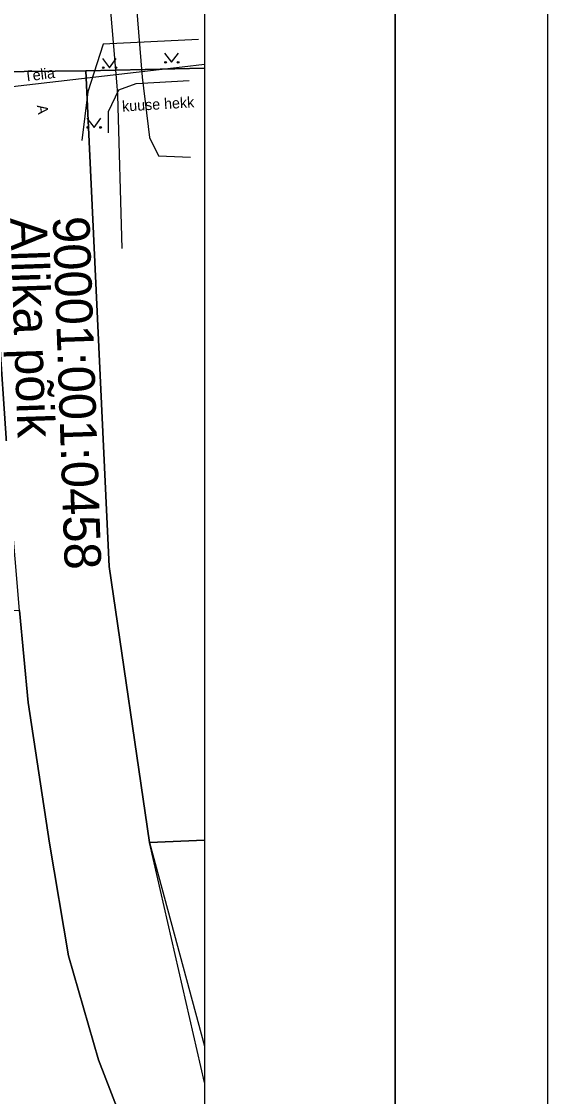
# Model space of a CAD drawing. Extents: x 648017 to 648227, y 6561313 to 6561610.
# Drawn here: x 648192.3 to 648226.8, y 6561440.1 to 6561510.6 of the extents above; entities that cross this region are included whole.
import ezdxf

# ---------------------------------------------------------------- set-up
doc = ezdxf.new("R2010")
doc.units = 0
for name, color, linetype in [('HALJASTUS', 7, 'Continuous'), ('PIIR', 7, 'Continuous'), ('SITRASS', 7, 'Continuous'), ('TEE', 7, 'Continuous'), ('VORMISTUS', 7, 'Continuous')]:
    doc.layers.add(name, color=color, linetype=linetype)

msp = doc.modelspace()

# ---------------------------------------------------------------- linework, layer by layer
at = {"layer": 'HALJASTUS'}
for p, q in [((648201.663, 6561508.575), (648202.126, 6561507.968)), ((648202.126, 6561507.968), (648202.572, 6561508.575)), ((648197.585, 6561508.218), (648198.048, 6561507.611)), ((648198.048, 6561507.611), (648198.494, 6561508.218)), ((648196.575, 6561504.296), (648197.038, 6561503.689)), ((648197.038, 6561503.689), (648197.484, 6561504.296))]:
    msp.add_line(p, q, dxfattribs=at)
msp.add_lwpolyline([(648197.976, 6561503.349), (648197.983, 6561504.737), (648198.654, 6561506.15), (648199.801, 6561506.568), (648203.285, 6561506.778)], dxfattribs=at)
for centre in [(648201.725, 6561507.968), (648202.554, 6561507.968), (648197.647, 6561507.611), (648198.476, 6561507.611), (648196.637, 6561503.689), (648197.466, 6561503.689)]:
    msp.add_circle(centre, 0.055, dxfattribs=at)
at = {"layer": 'PIIR'}
for points in [[(648204.275, 6561507.585), (648196.49, 6561507.4), (648190.43, 6561507.33), (648185.28, 6561507.91), (648181.07, 6561509.57), (648179.37, 6561510.62), (648184.89, 6561519.28), (648190.37, 6561530.46), (648195.16, 6561543.45), (648199.07, 6561558.2), (648199.342, 6561559.885)], [(648128.277, 6561349.885), (648122.86, 6561391.28), (648138.52, 6561393.32), (648130.76, 6561463.29), (648148.46, 6561478.24), (648163.17, 6561490.84), (648170.88, 6561497.65), (648175.42, 6561502.2), (648180.15, 6561508.27), (648181.07, 6561509.57), (648185.28, 6561507.91), (648190.43, 6561507.33), (648190.49, 6561494.61), (648191.59, 6561478.79), (648183.88, 6561478.99), (648183.75, 6561472.33), (648192.14, 6561472), (648192.72, 6561465.96), (648194.12, 6561456.75), (648195.36, 6561449.36), (648197.34, 6561442.54), (648200.74, 6561433.7), (648204.275, 6561426.345)], [(648204.275, 6561426.345), (648200.74, 6561433.7), (648197.34, 6561442.54), (648195.36, 6561449.36), (648194.12, 6561456.75), (648192.72, 6561465.96), (648192.14, 6561472), (648191.59, 6561478.79), (648190.49, 6561494.61), (648190.43, 6561507.33), (648196.49, 6561507.4), (648198.03, 6561474.9), (648200.68, 6561456.78), (648204.275, 6561443.421)], [(648204.275, 6561456.937), (648200.68, 6561456.78), (648198.03, 6561474.9), (648196.49, 6561507.4), (648204.275, 6561507.585)], [(648204.275, 6561441.053), (648200.68, 6561456.78), (648204.275, 6561456.937)]]:
    msp.add_lwpolyline(points, dxfattribs=at)
at = {"layer": 'SITRASS'}
for points in [[(648197.505, 6561531.025), (648197.445, 6561528.852), (648197.458, 6561525.301), (648197.48, 6561519.333), (648197.718, 6561516.251), (648197.987, 6561512.885), (648198.523, 6561506.414), (648198.572, 6561505.82), (648198.854, 6561495.748)], [(648199.292, 6561518.475), (648199.793, 6561511.816), (648200.197, 6561506.985), (648200.675, 6561503.04)], [(648199.292, 6561518.475), (648199.793, 6561511.816), (648200.197, 6561506.985), (648200.675, 6561503.04), (648201.255, 6561501.838), (648203.374, 6561501.744)], [(648135.65, 6561470.85), (648142, 6561476.76), (648149.47, 6561483.17), (648155.28, 6561488.02), (648163.02, 6561494.44), (648168.93, 6561499.19), (648171.97, 6561501.56), (648175.043, 6561503.606), (648175.92, 6561504.19), (648177.581, 6561504.785), (648179.44, 6561505.45), (648183.1, 6561505.79), (648187.09, 6561506.04), (648191.13, 6561506.32), (648202.808, 6561507.679), (648204.275, 6561507.849)]]:
    msp.add_lwpolyline(points, dxfattribs=at)
at = {"layer": 'TEE'}
msp.add_lwpolyline([(648203.885, 6561509.466), (648197.628, 6561509.161), (648196.629, 6561506.03), (648196.239, 6561502.843)], dxfattribs=at)
at = {"layer": 'VORMISTUS'}
for points in [[(648016.775, 6561609.885), (648226.775, 6561609.885), (648226.775, 6561312.885), (648016.775, 6561312.885)], [(648026.775, 6561323.885), (648216.775, 6561323.885), (648216.775, 6561598.885), (648026.775, 6561598.885)], [(648026.775, 6561598.885), (648216.775, 6561598.885), (648216.775, 6561323.885), (648026.775, 6561323.885)], [(648204.275, 6561349.885), (648039.275, 6561349.885), (648039.275, 6561559.885), (648204.275, 6561559.885)]]:
    msp.add_lwpolyline(points, close=True, dxfattribs=at)

# ---------------------------------------------------------------- texts
at = {"layer": 'HALJASTUS'}
msp.add_text('kuuse hekk', height=0.7, rotation=3.45512, dxfattribs=at).set_placement((648198.897, 6561504.729))
at = {"layer": 'PIIR'}
for s, p in [('Allika põik', (648191.534, 6561497.741)), ('90001:001:0458', (648194.332, 6561497.837))]:
    msp.add_text(s, height=2.4, rotation=271.95467, dxfattribs=at).set_placement(p)
at = {"layer": 'SITRASS'}
msp.add_text('Telia', height=0.7, rotation=6.9128, dxfattribs=at).set_placement((648192.486, 6561506.696))
at = {"layer": 'TEE'}
msp.add_text('A', height=0.7, rotation=277.6832, dxfattribs=at).set_placement((648193.281, 6561505.134))

doc.saveas('drawing.dxf')
